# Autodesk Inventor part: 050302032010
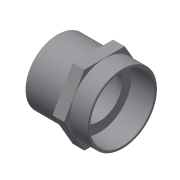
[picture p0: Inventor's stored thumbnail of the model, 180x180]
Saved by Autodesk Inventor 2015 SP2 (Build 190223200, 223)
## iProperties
Created: 2017-10
Part Number: 050302032010
Material: Generic
Description: PLASSON ADAPTOR SOCKET M.F. 32-1" CEM-THR
Document SubType Name: Modeling
Designer: KIM
Density: 1 g/cm^3
Appearance: Default
Author: KIM
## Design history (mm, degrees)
derived "050302.ipt"
feature "Solid1::050302.ipt"
tag "TaggingFeature1"
body "Solid1"
other parameters: "d0" = 51, "d2" = 36, "d3" = 30.291, "d4" = 22.4, "d8" = 35.84, "d13" = 0, "d14" = 0.32, "d16" = 12, "d17" = 22, "d18" = 24, "d19" = 32, "d20" = 25.6, "d_" = 32, "G_" = 30.291, "C_" = 36, "B_" = 12, "L_" = 22, "H_" = 51
